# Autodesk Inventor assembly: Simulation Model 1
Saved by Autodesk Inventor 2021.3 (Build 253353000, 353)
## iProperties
Created: 2022-12
Part Number: Simulation Model 1
Document SubType Name: Assembly
Designer: Administrator
Title: Simulation Model 1
Author: Administrator
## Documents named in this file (4)
- z:\worker\convert-fusion-r07\tmp\job-1\947\output\files\d8ec8b95-ea95-47b4-a131-b0593dda78df\3faabd23-e437-44f3-a80e-d8e332da8812.iam
- z:\worker\convert-fusion-r07\tmp\job-1\947\output\files\d8ec8b95-ea95-47b4-a131-b0593dda78df\VORON_V0.1_MGN7-1 v2.ipt
- z:\worker\convert-fusion-r07\tmp\job-1\947\output\files\d8ec8b95-ea95-47b4-a131-b0593dda78df\Plate X Beam Spacer v6.ipt
- z:\worker\convert-fusion-r07\tmp\job-1\947\output\files\d8ec8b95-ea95-47b4-a131-b0593dda78df\Part6.ipt
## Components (4 placed, 3 different names)
1. VORON_V0.1_MGN7-1 v2:1
2. Plate X Beam Spacer v6:1
3. Plate X Beam Spacer v6:2
4. Part6
